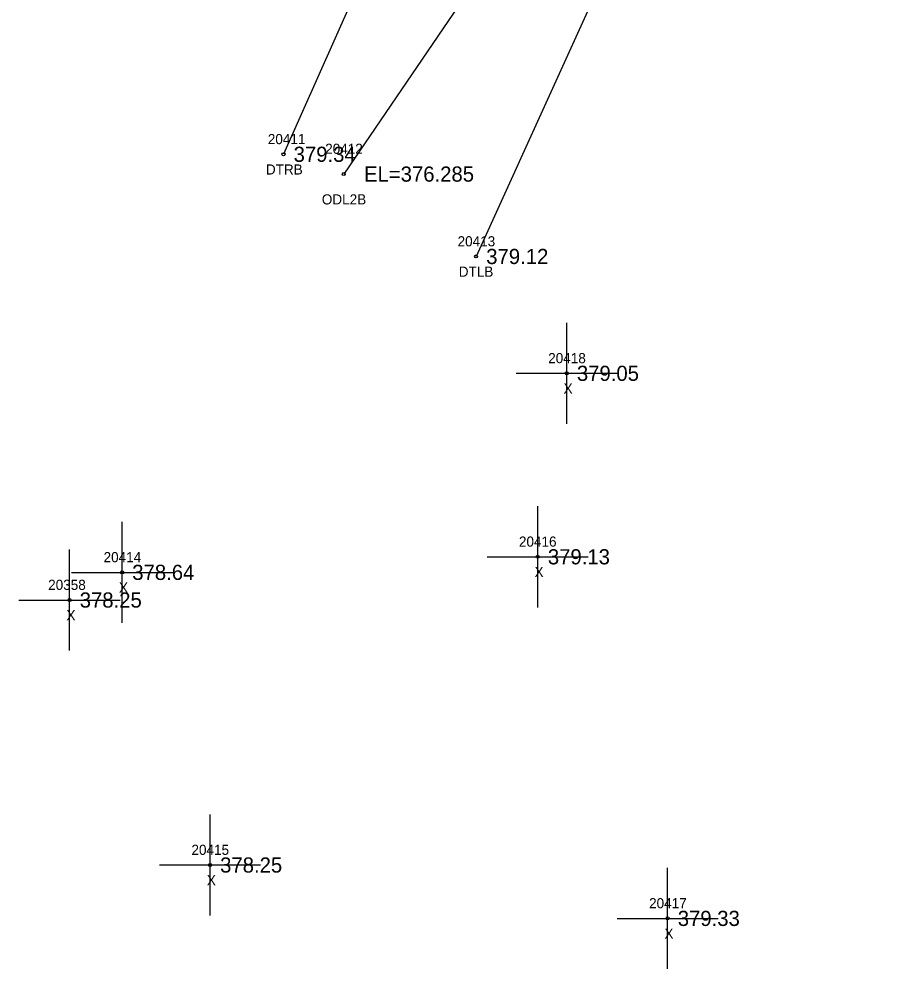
# Model space of a CAD drawing. Extents: x 2116373 to 2118139, y 979529 to 981026.
# Drawn here: x 2117651.7 to 2117737.2, y 980211.2 to 980305.1 of the extents above; entities that cross this region are included whole.
import ezdxf

# ---------------------------------------------------------------- set-up
doc = ezdxf.new("R2010")
doc.units = 0
for name, color, linetype in [('RD_EX_H2O', 7, 'Continuous'), ('RD_EX_H2O_txCode', 7, 'Continuous'), ('RD_EX_Misc', 7, 'Continuous'), ('RD_EX_Misc_txCode', 7, 'Continuous'), ('RD_EX_TX_H2O_ELEV', 7, 'Continuous'), ('RD_EX_TX_Misc_ELEV', 7, 'Continuous'), ('RD_SMD_Locator', 7, 'Continuous')]:
    doc.layers.add(name, color=color, linetype=linetype)

msp = doc.modelspace()

# ---------------------------------------------------------------- linework, layer by layer
at = {"layer": 'RD_EX_H2O'}
for points in [[(2117722.646, 980465.11), (2117718.051, 980457.795), (2117716.622, 980450.808), (2117716.233, 980440.059), (2117720.753, 980414.725), (2117720.731, 980398.853), (2117694.917, 980330.076), (2117677.85, 980291.736)], [(2117734.277, 980458.872), (2117732.864, 980417.748), (2117737.195, 980392.362), (2117713.634, 980318.483), (2117696.886, 980281.64)], [(2117725.143, 980456.946), (2117727.759, 980416.701), (2117729.697, 980399.954), (2117706.54, 980323.163), (2117683.803, 980289.781)]]:
    msp.add_lwpolyline(points, dxfattribs=at)
at = {"layer": 'RD_EX_Misc'}
for p, q in [((2117705.844, 980265.097), (2117705.844, 980275.097)), ((2117700.844, 980270.097), (2117710.844, 980270.097)), ((2117702.974, 980246.973), (2117702.974, 980256.973)), ((2117661.904, 980245.432), (2117661.904, 980255.432)), ((2117656.709, 980242.701), (2117656.709, 980252.701)), ((2117697.974, 980251.973), (2117707.974, 980251.973)), ((2117656.904, 980250.432), (2117666.904, 980250.432)), ((2117651.709, 980247.701), (2117661.709, 980247.701)), ((2117670.587, 980216.522), (2117670.587, 980226.522)), ((2117665.587, 980221.522), (2117675.587, 980221.522)), ((2117715.812, 980211.247), (2117715.812, 980221.247)), ((2117710.812, 980216.247), (2117720.812, 980216.247))]:
    msp.add_line(p, q, dxfattribs=at)
at = {"layer": 'RD_SMD_Locator'}
for centre in [(2117677.85, 980291.736), (2117683.803, 980289.781), (2117696.886, 980281.64), (2117705.844, 980270.097), (2117702.974, 980251.973), (2117661.904, 980250.432), (2117656.709, 980247.701), (2117670.587, 980221.522), (2117715.812, 980216.247)]:
    msp.add_circle(centre, 0.15, dxfattribs=at)

# ---------------------------------------------------------------- texts
at = {"layer": 'RD_EX_H2O_txCode'}
for s, p in [('20411', (2117676.299, 980292.736)), ('20412', (2117681.968, 980291.781)), ('DTRB', (2117676.11, 980289.736)), ('ODL2B', (2117681.637, 980286.781)), ('20413', (2117695.052, 980282.64)), ('DTLB', (2117695.17, 980279.64))]:
    msp.add_text(s, height=1, dxfattribs=at).set_placement(p)
at = {"layer": 'RD_EX_Misc_txCode'}
for s, p in [('20418', (2117704.009, 980271.097)), ('X', (2117705.529, 980268.097)), ('20416', (2117701.116, 980252.973)), ('20414', (2117660.069, 980251.432)), ('X', (2117702.659, 980249.973)), ('20358', (2117654.591, 980248.701)), ('X', (2117661.589, 980248.432)), ('X', (2117656.394, 980245.701)), ('20415', (2117668.752, 980222.522)), ('X', (2117670.272, 980219.522)), ('20417', (2117713.978, 980217.247)), ('X', (2117715.497, 980214.247))]:
    msp.add_text(s, height=1, dxfattribs=at).set_placement(p)
at = {"layer": 'RD_EX_TX_H2O_ELEV'}
for s, p in [('379.34', (2117678.85, 980290.986)), ('EL=376.285', (2117685.803, 980289.031)), ('379.12', (2117697.886, 980280.89))]:
    msp.add_text(s, height=1.5, dxfattribs=at).set_placement(p)
at = {"layer": 'RD_EX_TX_Misc_ELEV'}
for s, p in [('379.05', (2117706.844, 980269.347)), ('379.13', (2117703.974, 980251.223)), ('378.64', (2117662.904, 980249.682)), ('378.25', (2117657.709, 980246.951)), ('378.25', (2117671.587, 980220.772)), ('379.33', (2117716.812, 980215.497))]:
    msp.add_text(s, height=1.5, dxfattribs=at).set_placement(p)

doc.saveas('drawing.dxf')
